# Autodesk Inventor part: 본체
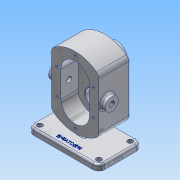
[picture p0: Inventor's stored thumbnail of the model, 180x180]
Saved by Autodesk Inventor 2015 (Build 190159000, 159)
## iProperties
Created: 2019-03
Part Number: 본체
Material: 알루미늄 6061
Document SubType Name: Modeling
Designer: user
Density: 2.7 g/cm^3
Appearance: 알루미늄 - 평지
Mass: 1188.24 g
Surface Area: 722.387 cm^2
Volume: 440.089 cm^3
Author: user
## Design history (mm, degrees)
sketch "스케치2"
  geometry: L1 (-60, -36.5)-(60, -36.5); L2 (60, -36.5)-(60, 36.5); L3 (60, 36.5)-(-60, 36.5); L4 (-60, 36.5)-(-60, -36.5); L5 (-60, -36.5)-(60, 36.5); L6 (60, -36.5)-(-60, 36.5); 1 further point
  constraints: 12 end point, 2 midpoint, 2 parallel, 1 horizontal, 1 perpendicular
  dimensions: "d2" = 120 distance of L2.end L3.end; "d3" = 73 distance of L1.end L2.end
extrude "돌출1" new body sketch "스케치2" distance "d4" = 10; taper "d5" = 0 deg
sketch "스케치3"
  geometry: L1 (120, 0)-(0, 0) reference; C1 r 60 at (60, -78); 2 further points
  constraints: 1 centre point, 1 midpoint, 1 vertical alignment
  dimensions: "d6" = 120 diameter of C1; "d7" = 78 distance from line of L1 C1.centre
extrude "돌출2" join sketch "스케치3" distance "d8" = 53; taper "d9" = 0 deg
sketch "스케치4"
  geometry: L1 (77.09, -63.961)-(40, -63.961); L2 (40, -63.961)-(40, 55.483); L3 (40, 55.483)-(77.09, 55.483); L4 (77.09, 55.483)-(77.09, -63.961); L5 (-40, -63.961)-(-71.773, -63.961); L6 (-71.773, -63.961)-(-71.773, 55.483); L7 (-71.773, 55.483)-(-40, 55.483); L8 (-40, 55.483)-(-40, -63.961); C1 r 60 at (0, 0) reference; 1 further point
  constraints: 16 end point, 4 parallel, 2 horizontal, 2 perpendicular, 2 point on line
  dimensions: "d11" = 40 distance from line of C1.centre L2; "d12" = 40 distance from line of L8 C1.centre
extrude "돌출3" cut sketch "스케치4" stored distance "d13" = 53; taper "d14" = 0 deg
sketch "스케치5"
  geometry: C1 r 19 at (60, -100); A1 r 60 centre (60, -78) between (100, -33.279) and (20, -33.279) reference; 1 further point
  constraints: 1 centre point, 1 vertical alignment
  dimensions: "d15" = 38 diameter of C1; "d16" = 22 distance of A1.centre C1.centre
extrude "돌출4" join sketch "스케치5" distance "d17" = 17; taper "d18" = 0 deg
sketch "스케치6"
  geometry: L1 (-36.5, 0)-(-36.5, 10) reference; L2 (-36.5, 10)-(36.5, 10) reference; L3 (36.5, 10)-(36.5, 0) reference; L4 (36.5, 0)-(-36.5, 0) reference; L5 (-16.5, 18)-(-16.5, 138) reference; L6 (-16.5, 138)-(36.5, 138) reference; L7 (36.5, 138)-(36.5, 119) reference; L8 (36.5, 119)-(53.5, 119) reference; L9 (53.5, 119)-(53.5, 81) reference; L10 (53.5, 81)-(36.5, 81) reference; L11 (36.5, 81)-(36.5, 18) reference; L12 (36.5, 18)-(-16.5, 18) reference; L13 (-6.5, 21.408)-(36.5, 21.408); L14 (36.5, 21.408)-(36.5, 7.41); L15 (36.5, 7.41)-(-6.5, 7.41); L16 (-6.5, 7.41)-(-6.5, 21.408); 1 further point
  constraints: 8 end point, 2 parallel, 1 horizontal, 1 perpendicular, 1 point on line
  dimensions: "d19" = 43 distance between parallel lines of L16 L14
extrude "돌출5" join sketch "스케치6" stored distance "d20" = 12; taper "d21" = 0 deg
sketch "스케치7"
  geometry: L1 (36, 100)-(36, 56); L2 (84, 100)-(84, 56); A1 r 60 centre (60, 78) between (100, 122.721) and (20, 122.721) reference; A2 r 24 centre (60, 100) between (84, 100) and (36, 100); A3 r 24 centre (60, 56) between (36, 56) and (84, 56); 1 further point
  constraints: 4 end point, 4 point on circle, 2 centre point, 2 horizontal alignment, 2 tangent, 2 vertical alignment
  dimensions: "d22" = 48 diameter of A2; "d23" = 22 distance of A1.centre A2.centre; "d24" = 48 diameter of A3; "d25" = 22 distance of A3.centre A1.centre
extrude "돌출6" cut sketch "스케치7" distance "d26" = 29; taper "d27" = 0 deg
sketch "스케치8"
  geometry: L1 (53.5, 81)-(36.5, 81) reference; L2 (36.5, 81)-(36.5, 0) reference; L3 (36.5, 0)-(-36.5, 0) reference; L4 (-36.5, 0)-(-36.5, 10) reference; L5 (-36.5, 10)-(-6.5, 10) reference; L6 (-6.5, 10)-(-6.5, 18) reference; L7 (-6.5, 18)-(-16.5, 18) reference; L8 (-16.5, 18)-(-16.5, 32) reference; L9 (-16.5, 32)-(12.5, 32) reference; L10 (12.5, 32)-(12.5, 124) reference; L11 (12.5, 124)-(-16.5, 124) reference; L12 (-16.5, 124)-(-16.5, 138) reference; L13 (-16.5, 138)-(36.5, 138) reference; L14 (36.5, 138)-(36.5, 119) reference; L15 (36.5, 119)-(53.5, 119) reference; L16 (53.5, 119)-(53.5, 81) reference; L17 (53.5, 100)-(12.5, 100); L18 (12.5, 112.5)-(27.5, 112.5); L19 (27.5, 112.5)-(27.5, 108.5); L20 (27.5, 108.5)-(46.2, 108.5); L21 (46.2, 108.5)-(46.2, 113.5); L22 (46.7, 114)-(52.8, 114); L23 (12.5, 100)-(12.5, 112.5); L24 (52.8, 114)-(53.5, 114.404); L25 (53.5, 114.404)-(53.5, 100); A1 r 0.5 centre (46.7, 113.5) between (46.7, 114) and (46.2, 113.5); 3 further points; 1 other entity
  constraints: 18 end point, 5 perpendicular, 5 point on line, 2 point on circle, 2 tangent, 1 centre point, 1 collinear, 1 horizontal, 1 horizontal alignment, 1 midpoint, 1 vertical, 2 other
  dimensions: "d28" = 15 distance between parallel lines of L10 L19; "d29" = 7.3 distance between parallel lines of L16 L21; "d30" = 30 deg angle of L22 L24; "d31" = 0.7 distance from line of L16 L22.end; "d32" = 0.5 radius of A1; "d33" = 28 diameter of L22 L17; "d34" = 17 diameter of L20 L17; "d35" = 25 diameter of L18 L17
revolve "회전1" sketch "스케치8" stored, may be unused: angle "d36" = 90 deg
sketch "스케치9"
  geometry: L1 (36.5, 119)-(53.5, 119) reference; L2 (53.5, 119)-(53.5, 114.404) reference; L3 (53.5, 114.404)-(52.8, 114) reference; L4 (52.8, 114)-(46.7, 114) reference; L5 (46.2, 113.5)-(46.2, 108.5) reference; L6 (46.2, 108.5)-(27.5, 108.5) reference; L7 (27.5, 108.5)-(27.5, 112.5) reference; L8 (27.5, 112.5)-(12.5, 112.5) reference; L9 (12.5, 112.5)-(12.5, 124) reference; L10 (12.5, 124)-(-16.5, 124) reference; L11 (-16.5, 124)-(-16.5, 138) reference; L12 (-16.5, 138)-(36.5, 138) reference; L13 (36.5, 138)-(36.5, 119) reference; L14 (53.5, 81)-(36.5, 81) reference; L15 (36.5, 81)-(36.5, 0) reference; L16 (36.5, 0)-(-36.5, 0) reference; L17 (-36.5, 0)-(-36.5, 10) reference; L18 (-36.5, 10)-(-6.5, 10) reference; L19 (-6.5, 10)-(-6.5, 18) reference; L20 (-6.5, 18)-(-16.5, 18) reference; L21 (-16.5, 18)-(-16.5, 32) reference; L22 (-16.5, 32)-(12.5, 32) reference; L23 (12.5, 32)-(12.5, 87.5) reference; L24 (12.5, 87.5)-(27.5, 87.5) reference; L25 (27.5, 87.5)-(27.5, 91.5) reference; L26 (27.5, 91.5)-(46.2, 91.5) reference; L27 (46.2, 91.5)-(46.2, 86.5) reference; L28 (46.7, 86)-(52.8, 86) reference; L29 (52.8, 86)-(53.5, 85.596) reference; L30 (53.5, 85.596)-(53.5, 81) reference; L31 (12.5, 68.5)-(27.5, 68.5); L32 (27.5, 68.5)-(27.5, 56); L33 (27.5, 56)-(12.5, 56); L34 (12.5, 56)-(12.5, 68.5); L35 (68.088, 100)-(-35.871, 100); A1 r 0.5 centre (46.7, 113.5) between (46.7, 114) and (46.2, 113.5) reference; A2 r 0.5 centre (46.7, 86.5) between (46.2, 86.5) and (46.7, 86) reference; 1 further point
  constraints: 10 end point, 2 horizontal, 2 parallel, 1 perpendicular, 1 point on line
  dimensions: "d37" = 8.5 distance between parallel lines of L35 L6; "d38" = 44 distance between parallel lines of L33 L35; "d39" = 25 diameter of L31 L33; "d40" = 15 distance between parallel lines of L34 L32
revolve "회전2" sketch "스케치9" stored, may be unused: angle "d41" = 90 deg
node "작업 평면1"
sketch "스케치10"
  geometry: L1 (-16.5, 33.279)-(-16.5, 122.721) reference; L2 (-36.5, 10)-(36.5, 10) reference; L3 (36.5, 10)-(36.5, 0) reference; L4 (36.5, 0)-(-36.5, 0) reference; L5 (-36.5, 0)-(-36.5, 10) reference; L6 (36.5, 138)-(-16.5, 138) reference; L7 (-6.5, 18)-(-16.5, 18) reference; L8 (67.752, 100)-(-71.921, 100); L9 (36.5, 119)-(53.5, 119) reference; L10 (53.5, 81)-(53.5, 119) reference; L11 (36.5, 119)-(36.5, 81) reference; L12 (36.5, 81)-(53.5, 81) reference; C1 r 11 at (-2.5, 78); 1 further point
  constraints: 2 end point, 1 centre point, 1 horizontal
  dimensions: "d43" = 22 diameter of C1; "d44" = 14 distance from line of L1 C1.centre; "d45" = 19 distance between parallel lines of L8 L9; "d46" = 22 distance from line of C1.centre L8
extrude "돌출7" join sketch "스케치10" stored distance "d47" = 29; taper "d48" = 0 deg
hole "구멍1" diameter "d51" = 8.917; stored, may be unused: countersink angle "d55" = 90 deg, drill point angle "d57" = 118 deg; dims "d49" = 10, "d50" = 10, "d52" = 20, "d53" = 4, "d54" = 2, "d56" = 25.1
sketch "스케치11"
  geometry: A1 r 24 centre (60, 100) between (84, 100) and (36, 100) reference; 2 further points
  constraints: 1 vertical alignment
  dimensions: "d58" = 31 distance of A1.centre point (60, 131)
hole "구멍2" sketch "스케치11" at (60, 131) diameter "d59" = 4.134; stored, may be unused: countersink angle "d63" = 90 deg, drill point angle "d65" = 120 deg; dims "d60" = 10, "d61" = 4, "d62" = 2, "d64" = 12
node "작업 평면2"
sketch "스케치12"
  geometry: L1 (-6, 36.5)-(-60, 36.5) reference; L2 (-60, 36.5)-(-60, -36.5) reference; C1 r 4.5 at (-50, 26.5); 1 further point
  constraints: 1 centre point
  dimensions: "d70" = 9 diameter of C1; "d71" = 10 distance from line of L1 C1.centre; "d72" = 10 distance from line of L2 C1.centre
extrude "돌출8" cut sketch "스케치12" stored distance "d73" = 29; taper "d74" = 0 deg
chamfer "모따기1" distance "d81" = 1; stored, may be unused: second distance "d82" = 2, angle "d83" = 45 deg
fillet "모깎기1" dims "d84" = 10
fillet "모깎기2" dims "d85" = 3
fillet "모깎기3" dims "d86" = 3
fillet "모깎기4" dims "d87" = 3
fillet "모깎기5" dims "d88" = 10
fillet "모깎기6" dims "d89" = 3
sketch "스케치13"
  geometry: L1 (-50, -36.5)-(50, -36.5) reference; L2 (-60, 26.5)-(-60, -26.5) reference; 2 further points
  constraints: 1 other
  dimensions: "d90" = 10 distance from line of L1 point (0, -26.5); "d91" = 60 distance from line of L2 point (0, -26.5)
feature "엠보싱1" sketch "스케치13" dims "d2" = 120, "d3" = 73, "d11" = 40, "d12" = 40, "d92" = 0.5, "d93" = 0
node "솔리드1"
mirror "대칭1"
pattern_circular "원형 패턴1" dims angle "d67" = 360 deg
mirror "대칭2"
pattern_linear "직사각형 패턴1" dims "d77" = 100, "d80" = 53
node "투영된 루프1"
node "절단 모서리 투영1"
node "절단 모서리 투영2"
node "절단 모서리 투영3"
node "절단 모서리 투영4"
other parameters: "d42" = 48, "d69" = 78
